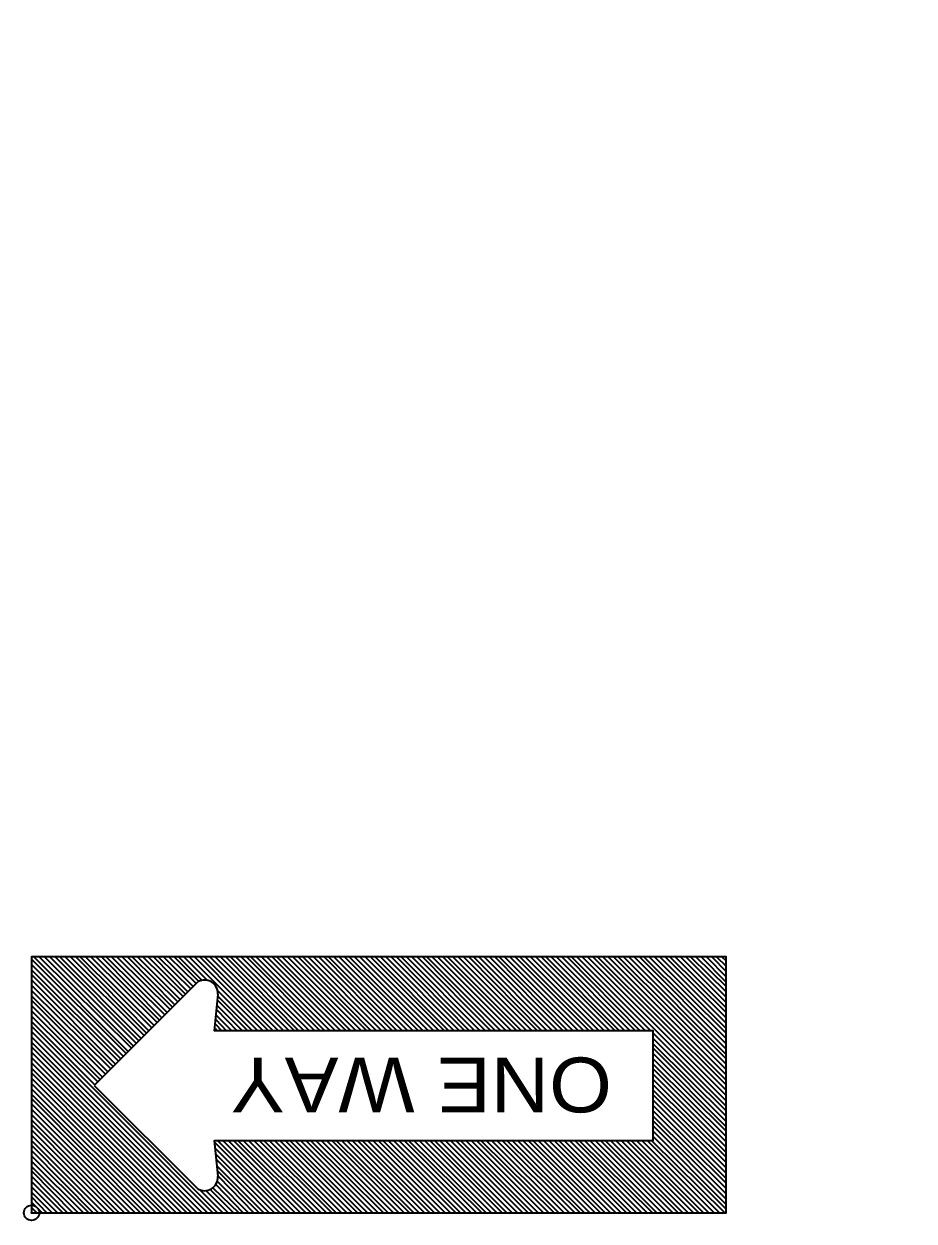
# Model space of a CAD drawing. Extents: x -198 to 658, y -402 to 142.
# Drawn here: x 331.19 to 359.23, y -0.1 to 37.63 of the extents above; entities that cross this region are included whole.
import ezdxf
from ezdxf.enums import TextEntityAlignment as Align

# ---------------------------------------------------------------- set-up
doc = ezdxf.new("R2010")
doc.units = 0
doc.header["$LTSCALE"] = 0.96
doc.header["$PDMODE"] = 32
doc.header["$PDSIZE"] = 0.48
doc.layers.add('1', color=7, linetype='Continuous', lineweight=35)

msp = doc.modelspace()

# ---------------------------------------------------------------- linework, layer by layer
at = {"layer": '1'}
for p, q in [((331.4271, 8.1548), (334.4031, 5.1788)), ((331.4271, 7.9868), (334.3071, 5.1068)), ((331.4991, 8.2268), (334.4751, 5.2508)), ((331.6671, 8.2268), (334.5711, 5.3468)), ((331.8351, 8.2268), (334.6431, 5.4188)), ((332.0031, 8.2268), (334.7151, 5.5148)), ((332.1711, 8.2268), (334.8111, 5.5868)), ((332.3151, 8.2268), (334.8831, 5.6588)), ((332.4831, 8.2268), (334.9791, 5.7548)), ((332.6511, 8.2268), (335.0511, 5.8268)), ((332.8191, 8.2268), (335.1231, 5.8988)), ((332.9631, 8.2268), (335.2191, 5.9948)), ((333.1311, 8.2268), (335.2911, 6.0668)), ((333.2991, 8.2268), (335.3871, 6.1628)), ((333.4671, 8.2268), (335.4591, 6.2348)), ((333.6351, 8.2268), (335.5311, 6.3068)), ((333.7791, 8.2268), (335.6271, 6.4028)), ((333.9471, 8.2268), (335.6991, 6.4748)), ((334.1151, 8.2268), (335.7951, 6.5708)), ((334.2831, 8.2268), (335.8671, 6.6428)), ((334.4511, 8.2268), (335.9391, 6.7148)), ((334.5951, 8.2268), (336.0351, 6.8108)), ((334.7631, 8.2268), (336.1071, 6.8828)), ((334.9311, 8.2268), (336.2031, 6.9788)), ((335.0991, 8.2268), (336.2751, 7.0508)), ((335.2671, 8.2268), (336.3471, 7.1228)), ((335.4111, 8.2268), (336.4431, 7.2188)), ((335.5791, 8.2268), (336.5151, 7.2908)), ((335.7471, 8.2268), (336.6111, 7.3868)), ((335.9151, 8.2268), (336.6831, 7.4588)), ((336.0591, 8.2268), (336.8031, 7.4828)), ((336.2271, 8.2268), (336.9711, 7.4828)), ((336.3951, 8.2268), (338.7231, 5.8988)), ((336.5631, 8.2268), (338.8911, 5.8988)), ((336.7311, 8.2268), (339.0351, 5.8988)), ((336.8751, 8.2268), (339.2031, 5.8988)), ((337.0431, 8.2268), (339.3711, 5.8988)), ((337.2111, 8.2268), (339.5391, 5.8988)), ((337.3791, 8.2268), (339.7071, 5.8988)), ((337.5471, 8.2268), (339.8511, 5.8988)), ((337.6911, 8.2268), (340.0191, 5.8988)), ((337.8591, 8.2268), (340.1871, 5.8988)), ((338.0271, 8.2268), (340.3551, 5.8988)), ((338.1951, 8.2268), (340.5231, 5.8988)), ((338.3391, 8.2268), (340.6671, 5.8988)), ((338.5071, 8.2268), (340.8351, 5.8988)), ((338.6751, 8.2268), (341.0031, 5.8988)), ((338.8431, 8.2268), (341.1711, 5.8988)), ((339.0111, 8.2268), (341.3391, 5.8988)), ((339.1551, 8.2268), (341.4831, 5.8988)), ((339.3231, 8.2268), (341.6511, 5.8988)), ((339.4911, 8.2268), (341.8191, 5.8988)), ((339.6591, 8.2268), (341.9871, 5.8988)), ((339.8271, 8.2268), (342.1311, 5.8988)), ((339.9711, 8.2268), (342.2991, 5.8988)), ((340.1391, 8.2268), (342.4671, 5.8988)), ((340.3071, 8.2268), (342.6351, 5.8988)), ((340.4751, 8.2268), (342.8031, 5.8988)), ((340.6431, 8.2268), (342.9471, 5.8988)), ((340.7871, 8.2268), (343.1151, 5.8988)), ((340.9551, 8.2268), (343.2831, 5.8988)), ((341.1231, 8.2268), (343.4511, 5.8988)), ((341.2911, 8.2268), (343.6191, 5.8988)), ((341.4351, 8.2268), (343.7631, 5.8988)), ((341.6031, 8.2268), (343.9311, 5.8988)), ((341.7711, 8.2268), (344.0991, 5.8988)), ((341.9391, 8.2268), (344.2671, 5.8988)), ((342.1071, 8.2268), (344.4351, 5.8988)), ((342.2511, 8.2268), (344.5791, 5.8988)), ((342.4191, 8.2268), (344.7471, 5.8988)), ((342.5871, 8.2268), (344.9151, 5.8988)), ((342.7551, 8.2268), (345.0831, 5.8988)), ((342.9231, 8.2268), (345.2271, 5.8988)), ((343.0671, 8.2268), (345.3951, 5.8988)), ((343.2351, 8.2268), (345.5631, 5.8988)), ((343.4031, 8.2268), (345.7311, 5.8988)), ((343.5711, 8.2268), (345.8991, 5.8988)), ((343.7391, 8.2268), (346.0431, 5.8988)), ((343.8831, 8.2268), (346.2111, 5.8988)), ((344.0511, 8.2268), (346.3791, 5.8988)), ((344.2191, 8.2268), (346.5471, 5.8988)), ((344.3871, 8.2268), (346.7151, 5.8988)), ((344.5311, 8.2268), (346.8591, 5.8988)), ((344.6991, 8.2268), (347.0271, 5.8988)), ((344.8671, 8.2268), (347.1951, 5.8988)), ((345.0351, 8.2268), (347.3631, 5.8988)), ((345.2031, 8.2268), (347.5071, 5.8988)), ((345.3471, 8.2268), (347.6751, 5.8988)), ((345.5151, 8.2268), (347.8431, 5.8988)), ((345.6831, 8.2268), (348.0111, 5.8988)), ((345.8511, 8.2268), (348.1791, 5.8988)), ((346.0191, 8.2268), (348.3231, 5.8988)), ((346.1631, 8.2268), (348.4911, 5.8988)), ((346.3311, 8.2268), (348.6591, 5.8988)), ((346.4991, 8.2268), (348.8271, 5.8988)), ((346.6671, 8.2268), (348.9951, 5.8988)), ((346.8111, 8.2268), (349.1391, 5.8988)), ((346.9791, 8.2268), (349.3071, 5.8988)), ((347.1471, 8.2268), (349.4751, 5.8988)), ((347.3151, 8.2268), (349.6431, 5.8988)), ((347.4831, 8.2268), (349.8111, 5.8988)), ((347.6271, 8.2268), (349.9551, 5.8988)), ((347.7951, 8.2268), (350.1231, 5.8988)), ((347.9631, 8.2268), (350.2911, 5.8988)), ((348.1311, 8.2268), (350.4591, 5.8988)), ((348.2991, 8.2268), (350.6031, 5.8988)), ((348.4431, 8.2268), (350.7711, 5.8988)), ((348.6111, 8.2268), (350.9391, 5.8988)), ((348.7791, 8.2268), (353.3151, 3.6908)), ((348.9471, 8.2268), (353.3151, 3.8588)), ((349.1151, 8.2268), (353.3151, 4.0268)), ((349.2591, 8.2268), (353.3151, 4.1948)), ((349.4271, 8.2268), (353.3151, 4.3388)), ((349.5951, 8.2268), (353.3151, 4.5068)), ((349.7631, 8.2268), (353.3151, 4.6748)), ((349.9071, 8.2268), (353.3151, 4.8428)), ((350.0751, 8.2268), (353.3151, 5.0108)), ((350.2431, 8.2268), (353.3151, 5.1548)), ((350.4111, 8.2268), (353.3151, 5.3228)), ((350.5791, 8.2268), (353.3151, 5.4908)), ((350.7231, 8.2268), (353.3151, 5.6588)), ((350.8911, 8.2268), (353.3151, 5.8268)), ((351.0591, 8.2268), (353.3151, 5.9708)), ((351.2271, 8.2268), (353.3151, 6.1388)), ((351.3951, 8.2268), (353.3151, 6.3068)), ((351.5391, 8.2268), (353.3151, 6.4748)), ((351.7071, 8.2268), (353.3151, 6.6188)), ((351.8751, 8.2268), (353.3151, 6.7868)), ((352.0431, 8.2268), (353.3151, 6.9548)), ((352.1871, 8.2268), (353.3151, 7.1228)), ((352.3551, 8.2268), (353.3151, 7.2908)), ((352.5231, 8.2268), (353.3151, 7.4348)), ((352.6911, 8.2268), (353.3151, 7.6028)), ((352.8591, 8.2268), (353.3151, 7.7708)), ((353.0031, 8.2268), (353.3151, 7.9388)), ((353.1711, 8.2268), (353.3151, 8.1068)), ((331.4271, 7.8188), (334.2351, 5.0108)), ((331.4271, 7.6748), (334.1631, 4.9388)), ((331.4271, 7.5068), (334.0671, 4.8428)), ((331.4271, 7.3388), (333.9951, 4.7708)), ((331.4271, 7.1708), (333.9231, 4.6988)), ((336.6591, 7.4348), (333.3951, 4.1708)), ((337.2831, 7.1708), (338.5551, 5.8988)), ((331.4271, 7.0028), (333.8271, 4.6028)), ((331.4271, 6.8588), (333.7551, 4.5308)), ((337.2831, 7.0028), (338.3871, 5.8988)), ((337.2831, 6.8588), (338.2431, 5.8988)), ((331.4271, 6.6908), (333.6591, 4.4348)), ((331.4271, 6.5228), (333.5871, 4.3628)), ((337.2591, 6.7148), (338.0751, 5.8988)), ((337.2591, 6.5708), (337.9071, 5.8988)), ((331.4271, 6.3548), (333.5151, 4.2908)), ((331.4271, 6.1868), (333.4191, 4.1948)), ((331.4271, 6.0428), (337.2831, 0.1628)), ((337.2111, 6.1148), (337.4271, 5.8988)), ((337.2351, 6.4028), (337.7391, 5.8988)), ((337.2351, 6.2588), (337.5711, 5.8988)), ((331.4271, 5.8748), (337.1391, 0.1628)), ((331.4271, 5.7068), (336.9711, 0.1628)), ((337.2111, 5.9708), (337.2591, 5.8988)), ((351.0111, 5.8268), (353.3151, 3.5228)), ((351.0111, 5.6588), (353.3151, 3.3788)), ((331.4271, 5.5388), (336.8031, 0.1628)), ((331.4271, 5.3948), (336.6351, 0.1628)), ((351.0111, 5.4908), (353.3151, 3.2108)), ((351.0111, 5.3468), (353.3151, 3.0428)), ((331.4271, 5.2268), (336.4671, 0.1628)), ((331.4271, 5.0588), (336.3231, 0.1628)), ((351.0111, 5.1788), (353.3151, 2.8748)), ((351.0111, 5.0108), (353.3151, 2.7308)), ((331.4271, 4.8908), (336.1551, 0.1628)), ((331.4271, 4.7228), (335.9871, 0.1628)), ((331.4271, 4.5788), (335.8191, 0.1628)), ((351.0111, 4.8428), (353.3151, 2.5628)), ((351.0111, 4.6988), (353.3151, 2.3948)), ((351.0111, 4.5308), (353.3151, 2.2268)), ((331.4271, 4.4108), (335.6511, 0.1628)), ((331.4271, 4.2428), (335.5071, 0.1628)), ((333.3951, 4.1708), (336.6591, 0.9308)), ((351.0111, 4.3628), (353.3151, 2.0588)), ((351.0111, 4.1948), (353.3151, 1.9148)), ((331.4271, 4.0748), (335.3391, 0.1628)), ((331.4271, 3.9068), (335.1711, 0.1628)), ((351.0111, 4.0268), (353.3151, 1.7468)), ((351.0111, 3.8828), (353.3151, 1.5788)), ((331.4271, 3.7628), (335.0031, 0.1628)), ((331.4271, 3.5948), (334.8591, 0.1628)), ((331.4271, 3.4268), (334.6911, 0.1628)), ((351.0111, 3.7148), (353.3151, 1.4108)), ((351.0111, 3.5468), (353.3151, 1.2428)), ((331.4271, 3.2588), (334.5231, 0.1628)), ((331.4271, 3.0908), (334.3551, 0.1628)), ((351.0111, 3.3788), (353.3151, 1.0988)), ((351.0111, 3.2108), (353.3151, 0.9308)), ((351.0111, 3.0668), (353.3151, 0.7628)), ((331.4271, 2.9468), (334.1871, 0.1628)), ((331.4271, 2.7788), (334.0431, 0.1628)), ((351.0111, 2.8988), (353.3151, 0.5948)), ((351.0111, 2.7308), (353.3151, 0.4268)), ((331.4271, 2.6108), (333.8751, 0.1628)), ((331.4271, 2.4428), (333.7071, 0.1628)), ((331.4271, 2.2988), (333.5391, 0.1628)), ((337.2111, 2.3708), (339.4191, 0.1628)), ((337.2831, 2.4428), (339.5631, 0.1628)), ((337.4511, 2.4428), (339.7311, 0.1628)), ((337.6191, 2.4428), (339.8991, 0.1628)), ((337.7871, 2.4428), (340.0671, 0.1628)), ((337.9311, 2.4428), (340.2351, 0.1628)), ((338.0991, 2.4428), (340.3791, 0.1628)), ((338.2671, 2.4428), (340.5471, 0.1628)), ((338.4351, 2.4428), (340.7151, 0.1628)), ((338.6031, 2.4428), (340.8831, 0.1628)), ((338.7471, 2.4428), (341.0271, 0.1628)), ((338.9151, 2.4428), (341.1951, 0.1628)), ((339.0831, 2.4428), (341.3631, 0.1628)), ((339.2511, 2.4428), (341.5311, 0.1628)), ((339.4191, 2.4428), (341.6991, 0.1628)), ((339.5631, 2.4428), (341.8431, 0.1628)), ((339.7311, 2.4428), (342.0111, 0.1628)), ((339.8991, 2.4428), (342.1791, 0.1628)), ((340.0671, 2.4428), (342.3471, 0.1628)), ((340.2111, 2.4428), (342.5151, 0.1628)), ((340.3791, 2.4428), (342.6591, 0.1628)), ((340.5471, 2.4428), (342.8271, 0.1628)), ((340.7151, 2.4428), (342.9951, 0.1628)), ((340.8831, 2.4428), (343.1631, 0.1628)), ((341.0271, 2.4428), (343.3311, 0.1628)), ((341.1951, 2.4428), (343.4751, 0.1628)), ((341.3631, 2.4428), (343.6431, 0.1628)), ((341.5311, 2.4428), (343.8111, 0.1628)), ((341.6991, 2.4428), (343.9791, 0.1628)), ((341.8431, 2.4428), (344.1231, 0.1628)), ((342.0111, 2.4428), (344.2911, 0.1628)), ((342.1791, 2.4428), (344.4591, 0.1628)), ((342.3471, 2.4428), (344.6271, 0.1628)), ((342.4911, 2.4428), (344.7951, 0.1628)), ((342.6591, 2.4428), (344.9391, 0.1628)), ((342.8271, 2.4428), (345.1071, 0.1628)), ((342.9951, 2.4428), (345.2751, 0.1628)), ((343.1631, 2.4428), (345.4431, 0.1628)), ((343.3071, 2.4428), (345.6111, 0.1628)), ((343.4751, 2.4428), (345.7551, 0.1628)), ((343.6431, 2.4428), (345.9231, 0.1628)), ((343.8111, 2.4428), (346.0911, 0.1628)), ((343.9791, 2.4428), (346.2591, 0.1628)), ((344.1231, 2.4428), (346.4031, 0.1628)), ((344.2911, 2.4428), (346.5711, 0.1628)), ((344.4591, 2.4428), (346.7391, 0.1628)), ((344.6271, 2.4428), (346.9071, 0.1628)), ((344.7951, 2.4428), (347.0751, 0.1628)), ((344.9391, 2.4428), (347.2191, 0.1628)), ((345.1071, 2.4428), (347.3871, 0.1628)), ((345.2751, 2.4428), (347.5551, 0.1628)), ((345.4431, 2.4428), (347.7231, 0.1628)), ((345.5871, 2.4428), (347.8911, 0.1628)), ((345.7551, 2.4428), (348.0351, 0.1628)), ((345.9231, 2.4428), (348.2031, 0.1628)), ((346.0911, 2.4428), (348.3711, 0.1628)), ((346.2591, 2.4428), (348.5391, 0.1628)), ((346.4031, 2.4428), (348.7071, 0.1628)), ((346.5711, 2.4428), (348.8511, 0.1628)), ((346.7391, 2.4428), (349.0191, 0.1628)), ((346.9071, 2.4428), (349.1871, 0.1628)), ((347.0751, 2.4428), (349.3551, 0.1628)), ((347.2191, 2.4428), (349.4991, 0.1628)), ((347.3871, 2.4428), (349.6671, 0.1628)), ((347.5551, 2.4428), (349.8351, 0.1628)), ((347.7231, 2.4428), (350.0031, 0.1628)), ((347.8911, 2.4428), (350.1711, 0.1628)), ((348.0351, 2.4428), (350.3151, 0.1628)), ((348.2031, 2.4428), (350.4831, 0.1628)), ((348.3711, 2.4428), (350.6511, 0.1628)), ((348.5391, 2.4428), (350.8191, 0.1628)), ((348.6831, 2.4428), (350.9871, 0.1628)), ((348.8511, 2.4428), (351.1311, 0.1628)), ((349.0191, 2.4428), (351.2991, 0.1628)), ((349.1871, 2.4428), (351.4671, 0.1628)), ((349.3551, 2.4428), (351.6351, 0.1628)), ((349.4991, 2.4428), (351.8031, 0.1628)), ((349.6671, 2.4428), (351.9471, 0.1628)), ((349.8351, 2.4428), (352.1151, 0.1628)), ((350.0031, 2.4428), (352.2831, 0.1628)), ((350.1711, 2.4428), (352.4511, 0.1628)), ((350.3151, 2.4428), (352.5951, 0.1628)), ((350.4831, 2.4428), (352.7631, 0.1628)), ((350.6511, 2.4428), (352.9311, 0.1628)), ((350.8191, 2.4428), (353.0991, 0.1628)), ((350.9631, 2.4428), (353.2671, 0.1628)), ((351.0111, 2.5628), (353.3151, 0.2828)), ((331.4271, 2.1308), (333.3711, 0.1628)), ((331.4271, 1.9628), (333.2271, 0.1628)), ((337.2111, 2.2028), (339.2511, 0.1628)), ((337.2351, 2.0108), (339.0831, 0.1628)), ((331.4271, 1.7948), (333.0591, 0.1628)), ((331.4271, 1.6268), (332.8911, 0.1628)), ((337.2591, 1.8428), (338.9151, 0.1628)), ((337.2591, 1.6508), (338.7471, 0.1628)), ((331.4271, 1.4828), (332.7231, 0.1628)), ((331.4271, 1.3148), (332.5551, 0.1628)), ((331.4271, 1.1468), (332.4111, 0.1628)), ((337.2831, 1.4828), (338.6031, 0.1628)), ((337.2831, 1.1468), (338.2671, 0.1628)), ((337.3071, 1.3148), (338.4351, 0.1628)), ((331.4271, 0.9788), (332.2431, 0.1628)), ((331.4271, 0.8108), (332.0751, 0.1628)), ((336.7311, 0.8828), (337.4511, 0.1628)), ((336.9231, 0.8588), (337.6191, 0.1628)), ((337.0431, 0.9068), (337.7871, 0.1628)), ((337.1391, 0.9548), (337.9551, 0.1628)), ((337.2351, 1.0508), (338.0991, 0.1628)), ((331.4271, 0.6668), (331.9071, 0.1628)), ((331.4271, 0.4988), (331.7631, 0.1628)), ((331.4271, 0.3308), (331.5951, 0.1628))]:
    msp.add_line(p, q, dxfattribs=at)
msp.add_lwpolyline([(331.4271, 0.1628), (353.3151, 0.1628), (353.3151, 8.2268), (331.4271, 8.2268)], close=True, dxfattribs=at)
msp.add_lwpolyline([(337.3071, 1.3148), (337.1871, 2.4428), (351.0111, 2.4428), (351.0111, 5.8988), (337.1871, 5.8988), (337.3071, 7.0508)], dxfattribs=at)
at = {"layer": '1', "lineweight": 53}
msp.add_arc((357.2472, 37.626), 60, 270, 0, dxfattribs=at)
at = {"layer": '1'}
for centre, start, end in [((336.8779, 7.0795), 356.63551, 121.23355), ((336.8779, 1.2792), 238.76645, 3.36449)]:
    msp.add_arc(centre, 0.419, start, end, dxfattribs=at)
msp.add_point((331.4271, 0.1628), dxfattribs=at)

# ---------------------------------------------------------------- texts
at = {"layer": '1', "width": 1.1}
msp.add_text('ONE WAY', height=1.728, rotation=180, dxfattribs=at).set_placement((343.7083, 5.0567), align=Align.CENTER)

doc.saveas('drawing.dxf')
